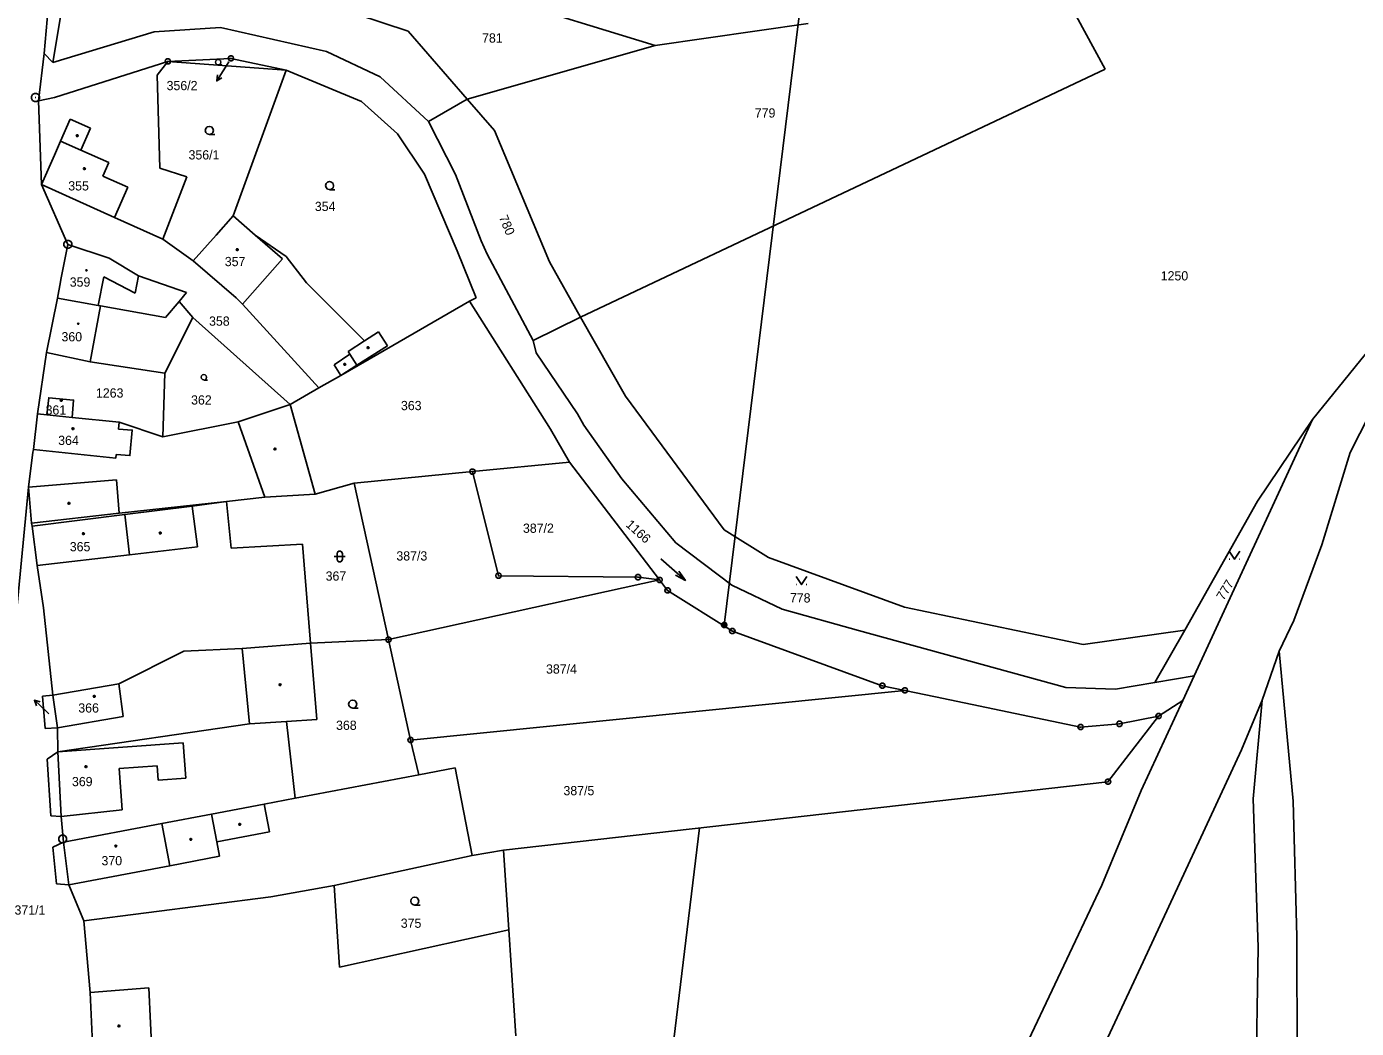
# Model space of a CAD drawing. Extents: x -812394 to -807601, y -1013098 to -1009266.
# Drawn here: x -811005.4 to -810760.5, y -1011411.9 to -1011227.4 of the extents above; entities that cross this region are included whole.
import ezdxf

# ---------------------------------------------------------------- set-up
doc = ezdxf.new("R2010")
doc.units = 0
for name, color, linetype in [('KN_HRANICE', 7, 'Continuous'), ('KN_KULTURY', 7, 'Continuous'), ('KN_MEZNIKY', 7, 'Continuous'), ('KN_PARCELY', 7, 'Continuous'), ('KN_SLUCKY', 7, 'Continuous'), ('KN_VEDENI', 7, 'Continuous')]:
    doc.layers.add(name, color=color, linetype=linetype)

# ---------------------------------------------------------------- blocks, each defined once
blk = doc.blocks.new('101')
blk.add_line((-0.05, 0), (0.05, 0))
blk.add_lwpolyline([(0.19, 0.72), (0.53, 0.53), (0.72, 0.19), (0.72, -0.2), (0.53, -0.54), (0.19, -0.73), (-0.2, -0.73), (-0.54, -0.54), (-0.73, -0.2), (-0.73, 0.19), (-0.54, 0.53), (-0.2, 0.72), (0.19, 0.72)])
blk = doc.blocks.new('304')
blk.add_lwpolyline([(0, 0), (-0.38, 0.1), (-0.65, 0.37), (-0.75, 0.74), (-0.65, 1.11), (-0.38, 1.38), (-0.01, 1.48), (0.36, 1.38), (0.63, 1.11), (0.73, 0.73), (0.63, 0.35), (0.36, 0.08), (-0.02, -0.02), (0.98, -0.02)])
blk = doc.blocks.new('314')
for p, q in [((-0.95, 0), (-0.85, 0)), ((0.85, 0), (0.95, 0))]:
    blk.add_line(p, q)
blk.add_lwpolyline([(-1, 1.5), (0, 0), (1, 1.5)])
blk = doc.blocks.new('316')
for points in [[(-1, 1), (0.27, 1), (1, 1)], [(-0.5, 1.5), (-0.4, 1.79), (-0.15, 1.97), (0.16, 1.97), (0.41, 1.79), (0.51, 1.5), (0.51, 0.5), (0.41, 0.21), (0.16, 0.03), (-0.15, 0.03), (-0.4, 0.21), (-0.5, 0.5), (-0.5, 1.5)]]:
    blk.add_lwpolyline(points)
blk = doc.blocks.new('802')
blk.add_line((-3, 0), (3, 0))
blk.add_lwpolyline([(1, 0.5), (3, 0), (1, -0.5)])
blk = doc.blocks.new('10292')
blk.add_line((0, 3), (0, 0))
blk.add_lwpolyline([(-0.5, 2), (0, 3), (0.5, 2)])
blk = doc.blocks.new('402')
blk.add_lwpolyline([(0.09, 0.15), (0.18, 0), (0.09, -0.15), (-0.09, -0.15), (-0.18, 0), (-0.09, 0.15), (0.09, 0.15)])
blk = doc.blocks.new('105')
blk.add_line((-0.12, 0), (0.12, 0))
blk.add_lwpolyline([(0.15, 0.48), (0.4, 0.3), (0.5, 0.01), (0.4, -0.28), (0.15, -0.46), (-0.16, -0.46), (-0.41, -0.28), (-0.51, 0.01), (-0.41, 0.3), (-0.16, 0.48), (0.15, 0.48)])
blk = doc.blocks.new('601')
blk.add_lwpolyline([(-0.15, 0.48), (0.16, 0.48), (0.41, 0.3), (0.51, 0.01), (0.41, -0.28), (0.16, -0.46), (-0.15, -0.46), (-0.4, -0.28), (-0.5, 0.01), (-0.4, 0.3), (-0.15, 0.48), (-0.12, 0.44), (0.12, 0.44), (0.28, 0.36), (-0.28, 0.36), (-0.36, 0.28), (0.36, 0.28), (0.36, 0.2), (-0.36, 0.2), (-0.4, 0.12), (0.4, 0.12), (0.44, 0.04), (-0.44, 0.04), (-0.44, -0.04), (0.44, -0.04), (0.41, -0.12), (-0.4, -0.12), (-0.39, -0.2), (0.42, -0.2), (0.37, -0.28), (-0.35, -0.28), (-0.27, -0.36), (0.29, -0.36), (0.18, -0.44), (-0.16, -0.44)])

msp = doc.modelspace()

# ---------------------------------------------------------------- linework, layer by layer
at = {"layer": 'KN_HRANICE'}
for p, q in [((-810806.75, -1011235.18), (-810824.69, -1011202.01)), ((-811002.17, -1011232.3), (-810999.64, -1011204.43)), ((-810889.59, -1011230.84), (-810947.19, -1011213.16)), ((-810965.7, -1011218.1), (-810935.11, -1011228.19)), ((-810861.45, -1011226.78), (-810889.59, -1011230.84)), ((-810981.89, -1011228.33), (-811000.55, -1011233.96)), ((-810969.64, -1011227.53), (-810981.89, -1011228.33)), ((-810950.13, -1011231.95), (-810969.64, -1011227.53)), ((-810935.11, -1011228.19), (-810924.23, -1011240.7)), ((-811003.16, -1011241.04), (-811002.17, -1011232.3)), ((-811000.55, -1011233.96), (-811002.17, -1011232.3)), ((-810940.26, -1011236.62), (-810950.13, -1011231.95)), ((-810924.23, -1011240.7), (-810889.59, -1011230.84)), ((-810979.36, -1011233.79), (-811000.25, -1011240.41)), ((-810981.35, -1011236.28), (-810979.36, -1011233.79)), ((-810967.75, -1011233.22), (-810979.36, -1011233.79)), ((-810979.36, -1011233.79), (-810957.6, -1011235.39)), ((-810957.6, -1011235.39), (-810967.75, -1011233.22)), ((-810980.83, -1011253.42), (-810981.35, -1011236.28)), ((-810957.6, -1011235.39), (-810967.33, -1011262.22)), ((-810943.72, -1011241.14), (-810957.6, -1011235.39)), ((-810931.35, -1011244.85), (-810940.26, -1011236.62)), ((-810903.34, -1011280.87), (-810806.75, -1011235.18)), ((-811000.25, -1011240.41), (-811003.16, -1011241.04)), ((-811002.62, -1011256.43), (-811003.16, -1011241.04)), ((-810937.08, -1011247.12), (-810943.72, -1011241.14)), ((-810931.35, -1011244.85), (-810924.23, -1011240.7)), ((-810924.23, -1011240.7), (-810919.19, -1011246.5)), ((-810926.38, -1011254.58), (-810931.35, -1011244.85)), ((-810919.19, -1011246.5), (-810909.08, -1011270.71)), ((-810932.1, -1011254.51), (-810937.08, -1011247.12)), ((-810975.86, -1011255.03), (-810980.83, -1011253.42)), ((-810989.17, -1011262.49), (-811002.62, -1011256.43)), ((-811002.62, -1011256.43), (-810997.78, -1011267.47)), ((-810980.3, -1011266.48), (-810975.86, -1011255.03)), ((-810926.1, -1011268.68), (-810932.1, -1011254.51)), ((-810921.65, -1011266.8), (-810926.38, -1011254.58)), ((-810980.3, -1011266.48), (-810989.17, -1011262.49)), ((-810967.33, -1011262.22), (-810970.46, -1011265.77)), ((-810967.33, -1011262.22), (-810963.3, -1011265.77)), ((-810974.72, -1011270.51), (-810980.3, -1011266.48)), ((-810970.46, -1011265.77), (-810974.72, -1011270.51)), ((-810963.3, -1011265.77), (-810957.54, -1011269.71)), ((-810999.06, -1011273.96), (-810997.78, -1011267.47)), ((-810997.78, -1011267.47), (-810990.19, -1011269.98)), ((-810922.58, -1011277.32), (-810926.1, -1011268.68)), ((-810920.56, -1011269.26), (-810921.65, -1011266.8)), ((-810990.19, -1011269.98), (-810984.79, -1011273.26)), ((-810974.72, -1011270.51), (-810966.78, -1011277.34)), ((-810957.54, -1011269.71), (-810953.85, -1011274.53)), ((-810912.07, -1011285.18), (-810920.56, -1011269.26)), ((-810909.08, -1011270.71), (-810903.34, -1011280.87)), ((-810999.13, -1011274.36), (-810999.06, -1011273.96)), ((-810975.9, -1011276.34), (-810984.79, -1011273.26)), ((-810999.71, -1011277.35), (-810999.13, -1011274.36)), ((-810977.29, -1011278), (-810975.9, -1011276.34)), ((-810953.85, -1011274.53), (-810943.16, -1011285.24)), ((-811001.73, -1011287.39), (-810999.71, -1011277.35)), ((-810999.71, -1011277.35), (-810992.18, -1011278.71)), ((-810992.18, -1011278.71), (-810991.74, -1011278.8)), ((-810991.74, -1011278.8), (-810979.77, -1011280.96)), ((-810979.77, -1011280.96), (-810977.29, -1011278)), ((-810974.77, -1011280.94), (-810977.29, -1011278)), ((-810965.64, -1011278.49), (-810966.78, -1011277.34)), ((-810951.55, -1011293.91), (-810965.64, -1011278.49)), ((-810923.78, -1011277.95), (-810922.58, -1011277.32)), ((-810923.78, -1011277.95), (-810908.87, -1011301.53)), ((-810979.92, -1011291.21), (-810974.77, -1011280.94)), ((-810956.84, -1011296.95), (-810974.77, -1011280.94)), ((-810903.34, -1011280.87), (-810912.07, -1011285.18)), ((-810895.09, -1011295.44), (-810903.34, -1011280.87)), ((-810768.55, -1011299.75), (-810752.37, -1011279.68)), ((-810940.55, -1011283.55), (-810943.16, -1011285.24)), ((-810938.93, -1011286.14), (-810940.55, -1011283.55)), ((-810944.54, -1011289.74), (-810938.93, -1011286.14)), ((-810911.54, -1011287.46), (-810912.07, -1011285.18)), ((-811001.73, -1011287.39), (-811003.39, -1011298.68)), ((-810993.66, -1011289.11), (-811001.73, -1011287.39)), ((-810903.9, -1011298.68), (-810911.54, -1011287.46)), ((-810979.92, -1011291.21), (-810993.66, -1011289.11)), ((-810947.5, -1011291.64), (-810944.54, -1011289.74)), ((-810980.3, -1011302.9), (-810979.92, -1011291.21)), ((-810951.55, -1011293.91), (-810947.5, -1011291.64)), ((-810956.84, -1011296.95), (-810951.55, -1011293.91)), ((-810876.93, -1011320.01), (-810895.09, -1011295.44)), ((-810956.84, -1011296.95), (-810966.4, -1011300.17)), ((-810956.84, -1011296.95), (-810952.23, -1011313.45)), ((-811003.39, -1011298.68), (-811004.13, -1011305.26)), ((-811003.39, -1011298.68), (-811001.63, -1011298.87)), ((-811001.63, -1011298.87), (-810997.01, -1011299.33)), ((-810997.01, -1011299.33), (-810988.33, -1011300.21)), ((-810988.33, -1011300.21), (-810980.3, -1011302.9)), ((-810966.4, -1011300.17), (-810980.3, -1011302.9)), ((-810902.75, -1011300.77), (-810903.9, -1011298.68)), ((-810895.77, -1011310.66), (-810902.75, -1011300.77)), ((-810768.55, -1011299.75), (-810790.34, -1011346.91)), ((-810768.55, -1011299.75), (-810778.68, -1011314.73)), ((-810905.37, -1011307.57), (-810908.87, -1011301.53)), ((-811004.22, -1011305.74), (-811005.05, -1011312.16)), ((-811004.13, -1011305.26), (-811004.22, -1011305.74)), ((-810923.25, -1011309.32), (-810905.37, -1011307.57)), ((-810905.37, -1011307.57), (-810888.79, -1011329.27)), ((-810945.05, -1011311.46), (-810923.25, -1011309.32)), ((-810923.25, -1011309.32), (-810918.46, -1011328.49)), ((-810885.8, -1011322.45), (-810895.77, -1011310.66)), ((-811011.64, -1011380.82), (-811005.05, -1011312.16)), ((-811005.05, -1011312.16), (-811004.45, -1011318.84)), ((-810952.23, -1011313.45), (-810945.05, -1011311.46)), ((-810945.05, -1011311.46), (-810938.72, -1011340.26)), ((-810988.35, -1011317), (-810968.58, -1011314.81)), ((-810968.58, -1011314.81), (-810961.52, -1011314.03)), ((-810967.67, -1011323.41), (-810968.58, -1011314.81)), ((-810961.52, -1011314.03), (-810952.23, -1011313.45)), ((-810778.68, -1011314.73), (-810792.06, -1011338.51)), ((-811004.45, -1011318.84), (-810988.35, -1011317)), ((-811004.45, -1011318.84), (-811004.32, -1011319.34)), ((-811004.32, -1011319.34), (-811003.44, -1011326.63)), ((-810868.75, -1011325.15), (-810876.93, -1011320.01)), ((-810967.67, -1011323.41), (-810954.58, -1011322.7)), ((-810954.58, -1011322.7), (-810953.07, -1011340.89)), ((-810875.48, -1011330.25), (-810885.8, -1011322.45)), ((-810843.66, -1011334.29), (-810868.75, -1011325.15)), ((-811002.26, -1011334.39), (-811003.44, -1011326.63)), ((-810888.79, -1011329.27), (-810938.72, -1011340.26)), ((-810892.77, -1011328.76), (-810918.46, -1011328.49)), ((-810892.77, -1011328.76), (-810888.79, -1011329.27)), ((-810888.79, -1011329.27), (-810887.31, -1011331.21)), ((-810866.23, -1011334.63), (-810875.48, -1011330.25)), ((-810875.38, -1011338.7), (-810887.31, -1011331.21)), ((-811000.52, -1011350.48), (-811002.26, -1011334.39)), ((-810852.14, -1011338.55), (-810866.23, -1011334.63)), ((-810810.76, -1011341.14), (-810843.66, -1011334.29)), ((-810847.78, -1011348.75), (-810875.38, -1011338.7)), ((-810813.95, -1011349.06), (-810852.14, -1011338.55)), ((-810792.06, -1011338.51), (-810810.76, -1011341.14)), ((-810797.6, -1011348.14), (-810792.06, -1011338.51)), ((-810976.43, -1011342.38), (-810988.41, -1011348.38)), ((-810965.69, -1011341.89), (-810976.43, -1011342.38)), ((-810965.69, -1011341.89), (-810953.07, -1011340.89)), ((-810938.72, -1011340.26), (-810953.07, -1011340.89)), ((-810953.07, -1011340.89), (-810951.91, -1011354.96)), ((-810938.72, -1011340.26), (-810934.65, -1011358.77)), ((-810777.84, -1011351.43), (-810774.7, -1011342.36)), ((-810774.7, -1011342.36), (-810772.09, -1011370.03)), ((-810790.34, -1011346.91), (-810797.6, -1011348.14)), ((-810790.34, -1011346.91), (-810792.45, -1011351.48)), ((-810988.41, -1011348.38), (-811000.52, -1011350.48)), ((-810934.65, -1011358.77), (-810843.62, -1011349.61)), ((-810843.62, -1011349.61), (-810847.78, -1011348.75)), ((-810838.01, -1011350.78), (-810843.62, -1011349.61)), ((-810804.84, -1011349.37), (-810813.95, -1011349.06)), ((-810797.6, -1011348.14), (-810804.84, -1011349.37)), ((-811000.52, -1011350.48), (-811002.43, -1011350.69)), ((-811002.43, -1011350.69), (-811001.96, -1011356.64)), ((-810999.69, -1011356.51), (-811000.52, -1011350.48)), ((-810811.26, -1011356.36), (-810838.01, -1011350.78)), ((-810800.11, -1011368.06), (-810792.45, -1011351.48)), ((-810792.45, -1011351.48), (-810796.89, -1011354.34)), ((-810806.21, -1011366.42), (-810796.89, -1011354.34)), ((-810796.89, -1011354.34), (-810804.09, -1011355.77)), ((-811001.96, -1011356.64), (-810999.69, -1011356.51)), ((-810999.65, -1011360.93), (-810999.69, -1011356.51)), ((-810964.33, -1011355.78), (-810999.65, -1011360.93)), ((-810964.33, -1011355.78), (-810957.53, -1011355.33)), ((-810957.53, -1011355.33), (-810951.91, -1011354.96)), ((-810957.53, -1011355.33), (-810955.9, -1011369.48)), ((-810804.09, -1011355.77), (-810811.26, -1011356.36)), ((-810934.65, -1011358.77), (-810933.12, -1011365.18)), ((-811001.56, -1011362.3), (-810999.65, -1011360.93)), ((-811000.89, -1011372.69), (-811001.56, -1011362.3)), ((-810933.12, -1011365.18), (-810926.42, -1011363.89)), ((-810926.42, -1011363.89), (-810923.32, -1011380.04)), ((-810955.9, -1011369.48), (-810933.12, -1011365.18)), ((-810917.53, -1011379.01), (-810806.21, -1011366.42)), ((-810961.6, -1011370.56), (-810955.9, -1011369.48)), ((-810807.37, -1011385.45), (-810800.11, -1011368.06)), ((-810971.34, -1011372.39), (-810961.6, -1011370.56)), ((-810772.09, -1011370.03), (-810771.46, -1011394.94)), ((-810999.02, -1011372.81), (-811000.89, -1011372.69)), ((-810998.61, -1011377.54), (-810999.02, -1011372.81)), ((-810998.61, -1011377.54), (-810980.47, -1011374.12)), ((-810980.47, -1011374.12), (-810971.34, -1011372.39)), ((-811000.53, -1011378.46), (-810998.61, -1011377.54)), ((-810999.85, -1011385.23), (-811000.53, -1011378.46)), ((-810923.32, -1011380.04), (-810917.53, -1011379.01)), ((-810916.55, -1011393.72), (-810917.53, -1011379.01)), ((-810923.32, -1011380.04), (-810948.75, -1011385.55)), ((-810997.58, -1011385.39), (-810999.85, -1011385.23)), ((-810994.85, -1011392.06), (-810997.58, -1011385.39)), ((-810960.37, -1011387.63), (-810948.75, -1011385.55)), ((-810947.72, -1011400.58), (-810948.75, -1011385.55)), ((-810835.54, -1011445.05), (-810807.37, -1011385.45)), ((-810994.85, -1011392.06), (-810960.37, -1011387.63)), ((-810994.85, -1011392.06), (-810993.69, -1011405.27)), ((-810916.55, -1011393.72), (-810947.72, -1011400.58)), ((-810915.25, -1011413.2), (-810916.55, -1011393.72)), ((-810771.46, -1011394.94), (-810771.36, -1011424.92)), ((-810992.93, -1011421.31), (-810993.69, -1011405.27))]:
    msp.add_line(p, q, dxfattribs=at)
for points in [[(-811000.55, -1011233.96), (-810996.85, -1011211.94), (-810995.36, -1011212.19)], [(-810947.5, -1011291.64), (-810940.71, -1011287.68), (-810923.78, -1011277.95)], [(-810774.7, -1011342.36), (-810771.98, -1011336.72), (-810766.82, -1011322.78), (-810761.61, -1011305.79), (-810758.06, -1011298.78), (-810747.85, -1011288.99), (-810732.24, -1011285.59), (-810715.58, -1011286.24), (-810702.36, -1011291.29), (-810686.79, -1011296.15)], [(-811001.63, -1011298.87), (-811001.31, -1011295.7), (-810996.71, -1011296.15), (-810997.01, -1011299.33)], [(-810817.11, -1011436.78), (-810799.71, -1011399.57), (-810781.64, -1011360.53), (-810777.84, -1011351.43)], [(-810777.84, -1011351.43), (-810779.49, -1011369.6), (-810778.58, -1011396.9), (-810779, -1011423.07), (-810780.56, -1011441.53), (-810782.41, -1011459.43)]]:
    msp.add_lwpolyline(points, dxfattribs=at)
at = {"layer": 'KN_PARCELY'}
for p, q in [((-810968.16, -1011233.85), (-810968.76, -1011234.82)), ((-811001.27, -1011353.91), (-811001.74, -1011353.47))]:
    msp.add_line(p, q, dxfattribs=at)
at = {"layer": 'KN_SLUCKY'}
for p, q in [((-810999.12, -1011248.48), (-810997.34, -1011244.43)), ((-810997.34, -1011244.43), (-810993.61, -1011246.08)), ((-810993.61, -1011246.08), (-810995.4, -1011250.12)), ((-811000.26, -1011251.07), (-810999.12, -1011248.48)), ((-810999.12, -1011248.48), (-810995.4, -1011250.12)), ((-811002.62, -1011256.43), (-811000.26, -1011251.07)), ((-810995.4, -1011250.12), (-810990.22, -1011252.41)), ((-810990.22, -1011252.41), (-810991.33, -1011254.91)), ((-810991.33, -1011254.91), (-810986.72, -1011256.95)), ((-810986.72, -1011256.95), (-810989.17, -1011262.49)), ((-810958.24, -1011270.15), (-810963.3, -1011265.77)), ((-810965.64, -1011278.49), (-810958.24, -1011270.15)), ((-810991.16, -1011273.46), (-810992.18, -1011278.71)), ((-810991.16, -1011273.46), (-810985.41, -1011276.45)), ((-810985.41, -1011276.45), (-810984.79, -1011273.26)), ((-810991.74, -1011278.8), (-810993.66, -1011289.11)), ((-810943.16, -1011285.24), (-810946.14, -1011287.17)), ((-810945.83, -1011287.68), (-810948.74, -1011289.66)), ((-810946.14, -1011287.17), (-810945.83, -1011287.68)), ((-810945.83, -1011287.68), (-810944.54, -1011289.74)), ((-810948.74, -1011289.66), (-810947.5, -1011291.64)), ((-810988.45, -1011301.47), (-810988.33, -1011300.21)), ((-810966.4, -1011300.17), (-810961.52, -1011314.03)), ((-811004.13, -1011305.26), (-810988.97, -1011306.82)), ((-810988.97, -1011306.82), (-810988.9, -1011306.14)), ((-810988.84, -1011310.82), (-811005.05, -1011312.16)), ((-810988.35, -1011317), (-810988.84, -1011310.82)), ((-810974.87, -1011315.67), (-810968.58, -1011314.81)), ((-811004.32, -1011319.34), (-810987.28, -1011317.22)), ((-810987.28, -1011317.22), (-810974.87, -1011315.67)), ((-810986.41, -1011324.63), (-810987.28, -1011317.22)), ((-810973.9, -1011323.16), (-810974.87, -1011315.67)), ((-811003.44, -1011326.63), (-810986.41, -1011324.63)), ((-810986.41, -1011324.63), (-810973.9, -1011323.16)), ((-810965.69, -1011341.89), (-810964.33, -1011355.78)), ((-810987.58, -1011354.41), (-810988.41, -1011348.38)), ((-810987.58, -1011354.41), (-810999.69, -1011356.51)), ((-810999.65, -1011360.93), (-810976.53, -1011359.27)), ((-810976.53, -1011359.27), (-810976.05, -1011365.75)), ((-810999.02, -1011372.81), (-810999.65, -1011360.93)), ((-810981.33, -1011363.48), (-810988.3, -1011364)), ((-810988.3, -1011364), (-810987.79, -1011371.62)), ((-810981.13, -1011366.12), (-810981.33, -1011363.48)), ((-810976.05, -1011365.75), (-810981.13, -1011366.12)), ((-810987.79, -1011371.62), (-810999.02, -1011372.81)), ((-810961.6, -1011370.56), (-810960.64, -1011375.67)), ((-810980.47, -1011374.12), (-810979.01, -1011381.89)), ((-810971.34, -1011372.39), (-810970.37, -1011377.51)), ((-810970.37, -1011377.51), (-810960.64, -1011375.67)), ((-810997.58, -1011385.39), (-810998.61, -1011377.54)), ((-810969.87, -1011380.16), (-810970.37, -1011377.51)), ((-810979.01, -1011381.89), (-810969.87, -1011380.16)), ((-810997.58, -1011385.39), (-810979.01, -1011381.89)), ((-810993.69, -1011405.27), (-810982.89, -1011404.38)), ((-810982.89, -1011404.38), (-810982.08, -1011420.69))]:
    msp.add_line(p, q, dxfattribs=at)
msp.add_lwpolyline([(-810988.45, -1011301.47), (-810985.92, -1011301.66), (-810986.34, -1011306.35), (-810988.9, -1011306.14)], dxfattribs=at)
at = {"layer": 'KN_VEDENI'}
for p, q in [((-810862.42, -1011220.06), (-810876.89, -1011337.57)), ((-810876.89, -1011337.57), (-810876.91, -1011337.74))]:
    msp.add_line(p, q, dxfattribs=at)
msp.add_lwpolyline([(-810881.42, -1011374.93), (-810888.67, -1011434.63), (-810899.49, -1011523.39), (-810905.13, -1011563.44)], dxfattribs=at)

# ---------------------------------------------------------------- block references
at = {"layer": 'KN_KULTURY', "xscale": 0.67, "yscale": 0.67}
for name, p in [('304', (-810970.08, -1011234.4)), ('402', (-810994.37, -1011272.23)), ('402', (-810995.85, -1011282.09)), ('304', (-810972.71, -1011292.44))]:
    msp.add_blockref(name, p, dxfattribs=at)
at = {"layer": 'KN_KULTURY'}
for name, p in [('304', (-810971.71, -1011247.21)), ('402', (-810996.06, -1011247.46)), ('402', (-810994.72, -1011253.52)), ('304', (-810949.56, -1011257.39)), ('402', (-810966.59, -1011268.43)), ('402', (-810942.47, -1011286.48)), ('402', (-810946.79, -1011289.56)), ('402', (-810999, -1011296.18)), ('402', (-810996.85, -1011301.42)), ('402', (-810959.65, -1011305.15)), ('402', (-810997.58, -1011315.14)), ('402', (-810980.77, -1011320.64)), ('402', (-810994.9, -1011320.73)), ('316', (-810947.7, -1011325.94)), ('314', (-810782.92, -1011325.46)), ('314', (-810862.65, -1011330.12)), ('402', (-810958.69, -1011348.58)), ('402', (-810992.92, -1011350.71)), ('304', (-810945.31, -1011352.87)), ('402', (-810994.46, -1011363.63)), ('402', (-810966.13, -1011374.29)), ('402', (-810988.94, -1011378.29)), ('402', (-810975.13, -1011377.06)), ('304', (-810933.89, -1011389.14)), ('402', (-810988.38, -1011411.41))]:
    msp.add_blockref(name, p, dxfattribs=at)
at = {"layer": 'KN_KULTURY', "rotation": -41.20628299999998}
msp.add_blockref('802', (-810886.31, -1011327.38), dxfattribs=at)
at = {"layer": 'KN_MEZNIKY'}
for name, p in [('105', (-810979.36, -1011233.79)), ('105', (-810967.75, -1011233.22)), ('101', (-811003.74, -1011240.41)), ('101', (-810997.76, -1011267.46)), ('105', (-810923.25, -1011309.32)), ('105', (-810918.46, -1011328.49)), ('105', (-810892.77, -1011328.76)), ('105', (-810888.79, -1011329.27)), ('105', (-810887.31, -1011331.21)), ('105', (-810938.72, -1011340.26)), ('105', (-810875.38, -1011338.7)), ('105', (-810847.78, -1011348.75)), ('105', (-810843.62, -1011349.61)), ('105', (-810796.89, -1011354.34)), ('105', (-810811.26, -1011356.36)), ('105', (-810804.09, -1011355.77)), ('105', (-810934.65, -1011358.77)), ('105', (-810806.21, -1011366.42)), ('101', (-810998.72, -1011376.98))]:
    msp.add_blockref(name, p, dxfattribs=at)
at = {"layer": 'KN_PARCELY'}
for p, rotation in [((-810968.76, -1011234.82), 148.224182), ((-811001.74, -1011353.47), 47.097131)]:
    msp.add_blockref('10292', p, dxfattribs=dict(at, rotation=rotation))
at = {"layer": 'KN_VEDENI'}
msp.add_blockref('601', (-810876.89, -1011337.57), dxfattribs=at)

# ---------------------------------------------------------------- texts
at = {"layer": 'KN_PARCELY'}
for s, height, p in [('781', 1.7, (-810921.49, -1011230.31)), ('356/2', 0.1, (-810968.4, -1011233.85)), ('356/2', 1.7, (-810979.59, -1011239.07)), ('779', 1.7, (-810871.26, -1011244.11)), ('356/1', 1.7, (-810975.55, -1011251.83)), ('355', 1.7, (-810997.7, -1011257.54)), ('354', 1.7, (-810952.29, -1011261.33)), ('357', 1.7, (-810968.87, -1011271.48)), ('359', 1.7, (-810997.43, -1011275.26)), ('1250', 1.7, (-810796.5, -1011274.11)), ('358', 1.7, (-810971.77, -1011282.45)), ('360', 1.7, (-810998.95, -1011285.33)), ('1263', 1.7, (-810992.6, -1011295.68)), ('362', 1.7, (-810975.08, -1011296.97)), ('361', 1.7, (-811001.88, -1011298.82)), ('363', 1.7, (-810936.43, -1011298)), ('364', 1.7, (-810999.56, -1011304.41)), ('387/2', 1.7, (-810913.96, -1011320.59)), ('365', 1.7, (-810997.42, -1011323.99)), ('387/3', 1.7, (-810937.27, -1011325.69)), ('367', 1.7, (-810950.3, -1011329.4)), ('387/4', 1.7, (-810909.71, -1011346.52)), ('366', 1.7, (-810995.85, -1011353.69)), ('371/2', 0.1, (-811001.51, -1011353.91)), ('368', 1.7, (-810948.38, -1011356.88)), ('369', 1.7, (-810997.02, -1011367.25)), ('387/5', 1.7, (-810906.5, -1011368.92)), ('370', 1.7, (-810991.58, -1011381.82)), ('371/1', 1.7, (-811007.6, -1011390.91)), ('375', 1.7, (-810936.46, -1011393.33))]:
    msp.add_text(s, height=height, dxfattribs=at).set_placement(p)
for s, rotation, p in [('780', 293.125, (-810918.44, -1011262.49)), ('1166', 318.049, (-810895.15, -1011319.27)), ('777', 58.27, (-810784.93, -1011333.16)), ('778', 359.359, (-810864.8, -1011333.39))]:
    msp.add_text(s, height=1.7, rotation=rotation, dxfattribs=at).set_placement(p)

doc.saveas('drawing.dxf')
